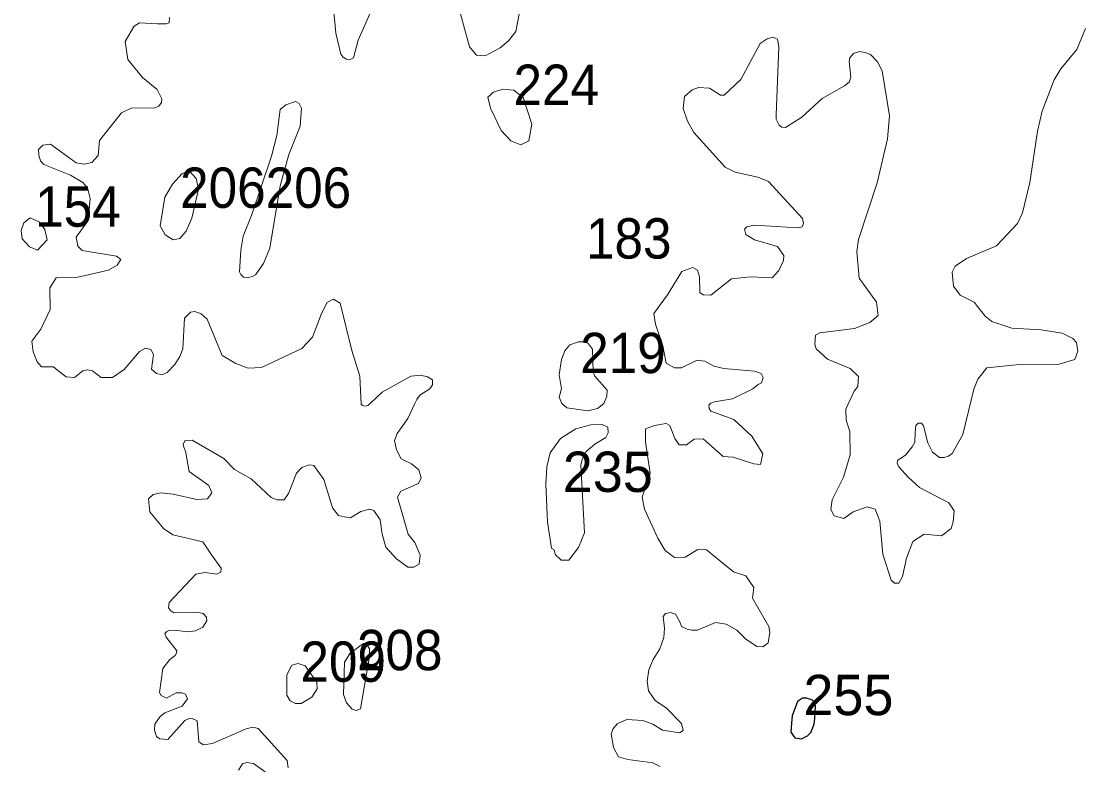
# Model space of a CAD drawing. Extents: x 499.9 to 555.3, y 9281.5 to 9336.8.
# Drawn here: x 531.687 to 535.902, y 9318.048 to 9320.996 of the extents above; entities that cross this region are included whole.
import ezdxf

# ---------------------------------------------------------------- set-up
doc = ezdxf.new("R2010")
doc.units = 0
doc.header["$LTSCALE"] = 0.064
doc.layers.add('1', color=7, linetype='Continuous', lineweight=25)
doc.layers.add('2', color=7, linetype='Continuous', lineweight=13)
doc.layers.add('21', color=7, linetype='Continuous')

msp = doc.modelspace()

# ---------------------------------------------------------------- linework, layer by layer
at = {"layer": '1'}
msp.add_lwpolyline([(534.7641, 9318.2991), (534.742, 9318.2417), (534.7398, 9318.213), (534.7376, 9318.1776), (534.7531, 9318.1555), (534.7796, 9318.1511), (534.8039, 9318.1622), (534.8171, 9318.1754), (534.8304, 9318.2085), (534.8326, 9318.2329), (534.8348, 9318.2815), (534.8238, 9318.3036), (534.7995, 9318.3124), (534.784, 9318.3124)], close=True, dxfattribs=at)
at = {"layer": '2'}
for points in [[(533.6286, 9321.0929), (533.6287, 9321.1259), (533.6434, 9321.176), (533.6602, 9321.2062), (533.6936, 9321.2341), (533.7271, 9321.2793), (533.7441, 9321.3288), (533.7427, 9321.3663), (533.7313, 9321.3942), (533.7039, 9321.4154), (533.6836, 9321.4604), (533.6861, 9321.5429), (533.6718, 9321.5701), (533.6455, 9321.5583), (533.5168, 9321.4), (533.4556, 9321.2382), (533.4241, 9321.0402), (533.4637, 9320.8945), (533.4912, 9320.8609), (533.5249, 9320.8586), (533.5854, 9320.8908), (533.6179, 9320.9183), (533.6467, 9320.9556), (533.6607, 9321.0243)], [(533.6268, 9320.5221), (533.6673, 9320.506), (533.6992, 9320.5212), (533.7106, 9320.5874), (533.6756, 9320.6938), (533.6386, 9320.7231), (533.5955, 9320.7263), (533.5583, 9320.7146), (533.5355, 9320.6947), (533.5463, 9320.6511), (533.5883, 9320.5629)], [(532.5659, 9320.1437), (532.5998, 9320.2263), (532.6786, 9320.4608), (532.6993, 9320.5435), (532.7124, 9320.6454), (532.7348, 9320.6651), (532.774, 9320.6772), (532.7884, 9320.6697), (532.798, 9320.6508), (532.7918, 9320.5799), (532.7473, 9320.4678), (532.7123, 9320.3437), (532.6714, 9320.0958), (532.6473, 9320.0357), (532.6152, 9319.9912), (532.6058, 9319.9853), (532.5875, 9319.9805), (532.5673, 9319.9815), (532.5564, 9319.9925), (532.5518, 9320.0022), (532.5564, 9320.0884)], [(532.2564, 9320.1487), (532.2373, 9320.1849), (532.2553, 9320.2982), (532.2863, 9320.3501), (532.3245, 9320.3929), (532.3535, 9320.401), (532.38, 9320.3726), (532.3887, 9320.3298), (532.3633, 9320.2157), (532.3401, 9320.1638), (532.3154, 9320.1341), (532.289, 9320.1292)], [(531.719, 9320.1018), (531.69, 9320.1335), (531.6865, 9320.1664), (531.6971, 9320.1971), (531.7217, 9320.2161), (531.7589, 9320.1992), (531.7801, 9320.1702), (531.7887, 9320.1292), (531.751, 9320.0879)], [(533.8286, 9319.5386), (533.8189, 9319.5058), (533.8288, 9319.4801), (533.8489, 9319.4634), (533.9325, 9319.4518), (533.9712, 9319.4607), (533.9956, 9319.4807), (534.0073, 9319.51), (534.0085, 9319.5331), (533.9599, 9319.5888), (533.9535, 9319.6048), (533.9506, 9319.6963), (533.9356, 9319.7168), (533.9201, 9319.7247), (533.8961, 9319.7248), (533.8617, 9319.7134), (533.8418, 9319.6896), (533.8284, 9319.655), (533.8183, 9319.5947)], [(533.7729, 9319.0118), (533.7655, 9319.1605), (533.7701, 9319.2296), (533.7826, 9319.2851), (533.8242, 9319.3414), (533.885, 9319.3801), (533.9447, 9319.3957), (533.9894, 9319.3969), (534.0112, 9319.3868), (534.0135, 9319.3644), (534.0044, 9319.3459), (533.96, 9319.3193), (533.9256, 9319.2902), (533.9111, 9319.2629), (533.9051, 9319.2372), (533.9187, 9318.9671), (533.896, 9318.9091), (533.8568, 9318.8587), (533.8273, 9318.8593), (533.8047, 9318.8806), (533.7975, 9318.9014), (533.7883, 9318.9074)], [(532.9683, 9318.4555), (532.9633, 9318.3263), (532.9759, 9318.2932), (532.9979, 9318.2682), (533.014, 9318.2634), (533.031, 9318.2695), (533.0672, 9318.4777), (533.0672, 9318.5072), (533.0568, 9318.5255), (533.0428, 9318.5286), (532.99, 9318.4905)], [(532.8578, 9318.3761), (532.8123, 9318.4403), (532.784, 9318.4493), (532.7585, 9318.4425), (532.739, 9318.4052), (532.7397, 9318.3236), (532.7523, 9318.3016), (532.7735, 9318.2906), (532.7962, 9318.2913), (532.8384, 9318.3156), (532.8589, 9318.349)]]:
    msp.add_lwpolyline(points, close=True, dxfattribs=at)
for points in [[(533.0786, 9321.0494), (533.0214, 9320.9205), (533.0031, 9320.8503), (532.9901, 9320.8443), (532.9751, 9320.8455), (532.9613, 9320.8545), (532.9533, 9320.866), (532.9341, 9320.9483), (532.9252, 9321.0352)], [(532.2738, 9321.0111), (532.2722, 9320.9903), (532.261, 9320.9859), (532.226, 9320.9853), (532.1547, 9320.9894), (532.1347, 9320.977), (532.0981, 9320.9159), (532.109, 9320.8442), (532.1669, 9320.7729), (532.2255, 9320.7248), (532.2438, 9320.6882), (532.2427, 9320.6738), (532.2315, 9320.6591), (532.2163, 9320.6528), (532.1221, 9320.6511), (532.0832, 9320.6327), (531.9972, 9320.5236), (531.9908, 9320.4641), (531.9667, 9320.436), (531.9355, 9320.4298), (531.9039, 9320.4346), (531.8019, 9320.5088), (531.7724, 9320.5044), (531.7545, 9320.4878), (531.7557, 9320.4644), (531.7633, 9320.4424), (531.776, 9320.4286), (531.8814, 9320.3851), (531.9307, 9320.3563), (531.9484, 9320.3349), (531.9592, 9320.2928)], [(535.5147, 9319.6221), (535.6305, 9319.6338), (535.796, 9319.6354), (535.8632, 9319.6548), (535.8748, 9319.6881), (535.8696, 9319.7229), (535.8549, 9319.7377), (535.8133, 9319.7592), (535.7299, 9319.7723), (535.6138, 9319.7785), (535.5344, 9319.8053), (535.5071, 9319.8265), (535.4638, 9319.882), (535.4079, 9319.91), (535.3816, 9319.9459), (535.3765, 9320.0014), (535.3891, 9320.025), (535.4332, 9320.0551), (535.5522, 9320.1056), (535.6358, 9320.1941), (535.6558, 9320.237), (535.6853, 9320.3564), (535.7145, 9320.5603), (535.7331, 9320.6397), (535.7809, 9320.7639), (535.8074, 9320.8068), (535.8714, 9320.8833), (535.9048, 9320.9677)], [(534.3271, 9320.5998), (534.3099, 9320.65), (534.3163, 9320.6974), (534.3459, 9320.7242), (534.3715, 9320.7335), (534.4151, 9320.7302), (534.4585, 9320.7027), (534.473, 9320.7025), (534.5392, 9320.7656), (534.6156, 9320.9081), (534.6429, 9320.9261), (534.666, 9320.9333), (534.6846, 9320.9248), (534.6901, 9320.8947), (534.6795, 9320.6246), (534.6792, 9320.6077), (534.691, 9320.5844), (534.701, 9320.5758), (534.7164, 9320.5745), (534.7806, 9320.616), (534.862, 9320.6901), (534.9495, 9320.7399), (534.968, 9320.7544), (534.9753, 9320.7743), (534.969, 9320.8364), (534.9717, 9320.851), (534.9854, 9320.8686), (535.01, 9320.8756), (535.0311, 9320.8725), (535.0528, 9320.8638), (535.0804, 9320.8353), (535.0992, 9320.7996), (535.1281, 9320.6214), (535.1206, 9320.5302), (535.079, 9320.3558), (535.0051, 9320.1306), (534.9994, 9320.0835), (535.0075, 9319.9767), (535.0764, 9319.882), (535.0837, 9319.8295), (535.0507, 9319.8012), (534.989, 9319.7774), (534.8523, 9319.7601), (534.8356, 9319.7507), (534.8324, 9319.716), (534.8381, 9319.6975), (534.882, 9319.6556), (534.9722, 9319.6194), (535.0055, 9319.5875), (535.0022, 9319.5481), (534.988, 9319.5297), (534.955, 9319.458), (534.9565, 9319.4142), (534.9706, 9319.3697), (534.9723, 9319.2774), (534.9455, 9319.189), (534.9008, 9319.0991), (534.8963, 9319.0596), (534.9095, 9319.0354), (534.9479, 9319.0246), (534.9844, 9319.0508), (535.0392, 9319.0702), (535.0712, 9319.0614), (535.0902, 9319.0145), (535.1014, 9318.8826), (535.1348, 9318.7794), (535.1485, 9318.7687), (535.1656, 9318.7684), (535.1793, 9318.7942), (535.1955, 9318.8674), (535.2212, 9318.9339), (535.2652, 9318.9619), (535.3341, 9318.9564), (535.3726, 9318.9842), (535.3813, 9319.0108), (535.3842, 9319.0544), (535.3637, 9319.0862), (535.2478, 9319.148), (535.2036, 9319.187), (535.1639, 9319.2305), (535.1591, 9319.2433), (535.1607, 9319.2538), (535.1933, 9319.2773), (535.2188, 9319.308), (535.2291, 9319.3269), (535.2298, 9319.3638), (535.2334, 9319.3928), (535.2416, 9319.403), (535.2554, 9319.4031), (535.2631, 9319.3916), (535.2807, 9319.3248), (535.2995, 9319.2874), (535.3267, 9319.2668), (535.3454, 9319.2667), (535.3628, 9319.272)], [(534.6488, 9320.3602), (534.6069, 9320.3784), (534.5164, 9320.3982), (534.4775, 9320.4171), (534.3532, 9320.5555), (534.3271, 9320.5998)], [(534.2307, 9318.6359), (534.2408, 9318.6477), (534.2606, 9318.6512), (534.2797, 9318.6451), (534.2975, 9318.6143), (534.3039, 9318.5969), (534.3262, 9318.5852), (534.3443, 9318.5814), (534.3675, 9318.5821), (534.4383, 9318.6119), (534.4803, 9318.606), (534.5235, 9318.5817), (534.5575, 9318.548), (534.6031, 9318.5169), (534.6268, 9318.5154), (534.6476, 9318.5318), (534.6539, 9318.5739), (534.6506, 9318.5961), (534.5848, 9318.709), (534.5903, 9318.7509), (534.5593, 9318.7969), (534.5101, 9318.8131), (534.4033, 9318.9), (534.3684, 9318.9015), (534.3181, 9318.8707), (534.2758, 9318.8694), (534.2392, 9318.8981), (534.21, 9318.9463), (534.1575, 9319.0619), (534.1483, 9319.1085), (534.1795, 9319.2041), (534.1609, 9319.3265), (534.1609, 9319.3796), (534.1964, 9319.3937), (534.2427, 9319.4011), (534.2579, 9319.3934), (534.2772, 9319.3412), (534.2945, 9319.3168), (534.3241, 9319.3168), (534.3537, 9319.3394), (534.3897, 9319.3405), (534.4688, 9319.2697), (534.5093, 9319.2674), (534.5911, 9319.2407), (534.6164, 9319.2389), (534.6266, 9319.2811), (534.5832, 9319.351), (534.5111, 9319.4169), (534.4197, 9319.4504), (534.4134, 9319.4608), (534.4125, 9319.4732), (534.4205, 9319.4816), (534.4351, 9319.4874), (534.5062, 9319.4993), (534.5871, 9319.5384), (534.6073, 9319.5563), (534.6216, 9319.563), (534.6272, 9319.5833), (534.6203, 9319.599), (534.5933, 9319.6085), (534.4718, 9319.6197), (534.432, 9319.629), (534.3968, 9319.6478), (534.3657, 9319.6526), (534.3038, 9319.6214), (534.2762, 9319.6215), (534.2436, 9319.6405), (534.2302, 9319.7089), (534.2008, 9319.7955), (534.1945, 9319.8374), (534.2481, 9319.9108), (534.3051, 9320.0038), (534.3489, 9320.0201), (534.3676, 9320.0086), (534.3753, 9319.9832), (534.3769, 9319.9203), (534.3899, 9319.9108), (534.42, 9319.9103), (534.5019, 9319.9746), (534.5769, 9319.9824), (534.6633, 9319.9781), (534.6898, 9320.008), (534.708, 9320.0477), (534.7099, 9320.0674), (534.6842, 9320.1024), (534.5936, 9320.129), (534.5588, 9320.1501), (534.5531, 9320.1712), (534.5625, 9320.1813), (534.5915, 9320.1875), (534.7661, 9320.1768), (534.7826, 9320.1802), (534.7874, 9320.1941), (534.7841, 9320.2133), (534.6488, 9320.3602)], [(531.9592, 9320.2928), (531.9516, 9320.2055), (531.9042, 9320.1398), (531.9108, 9320.1045), (531.9284, 9320.0874), (532.0644, 9320.065)], [(532.0644, 9320.065), (532.0813, 9320.0507), (532.0669, 9320.0283), (532.0318, 9320.0084), (531.9102, 9319.9812), (531.8245, 9319.9793), (531.7991, 9319.9394), (531.8006, 9319.8535), (531.7641, 9319.7746), (531.729, 9319.7269), (531.7331, 9319.6848), (531.7491, 9319.6458), (531.7671, 9319.6263), (531.8142, 9319.6256), (531.8313, 9319.6111), (531.8641, 9319.586), (531.8978, 9319.5833), (531.9309, 9319.6098), (531.9492, 9319.614), (531.9688, 9319.6097), (532.0032, 9319.583), (532.0482, 9319.5834), (532.0946, 9319.6148), (532.1553, 9319.686), (532.1793, 9319.6993), (532.2005, 9319.6942), (532.2113, 9319.6744), (532.207, 9319.6454), (532.2027, 9319.6166), (532.2226, 9319.5998), (532.2451, 9319.5945), (532.2645, 9319.6027), (532.2954, 9319.6346), (532.3146, 9319.6674), (532.3269, 9319.6976), (532.3338, 9319.8184), (532.3575, 9319.8421), (532.3742, 9319.8452), (532.3993, 9319.836), (532.4228, 9319.8145), (532.4828, 9319.6713), (532.5366, 9319.639), (532.5863, 9319.6203), (532.6383, 9319.6228), (532.7987, 9319.6982), (532.8414, 9319.7429), (532.8761, 9319.8369), (532.8993, 9319.8804), (532.9239, 9319.8943), (532.9511, 9319.8781), (532.9972, 9319.6912), (533.0288, 9319.5893), (533.0338, 9319.4784), (533.0386, 9319.4723), (533.0501, 9319.4695), (533.0607, 9319.4723), (533.0728, 9319.4825), (533.1167, 9319.5255), (533.2313, 9319.5892), (533.2693, 9319.5923), (533.2966, 9319.5861), (533.3168, 9319.5742), (533.3161, 9319.5546), (533.3056, 9319.5383), (533.2659, 9319.5128), (533.2547, 9319.4958), (533.2467, 9319.4808), (533.2187, 9319.4205), (533.1763, 9319.3613), (533.1662, 9319.3336), (533.174, 9319.2965), (533.1927, 9319.2607), (533.2332, 9319.2416), (533.2621, 9319.2172), (533.272, 9319.1852), (533.2611, 9319.163), (533.1911, 9319.1333), (533.1774, 9319.1095), (533.2208, 9318.963), (533.2473, 9318.9296), (533.2676, 9318.8796), (533.2633, 9318.8428), (533.2427, 9318.8314), (533.2185, 9318.8314), (533.1739, 9318.8652), (533.1315, 9318.9108), (533.1166, 9318.9623), (533.1099, 9319.0194), (533.0846, 9319.0558), (533.0681, 9319.0621), (533.0322, 9319.0518), (532.9917, 9319.0265), (532.9679, 9319.0314), (532.9441, 9319.0364), (532.9204, 9319.0666)], [(535.3628, 9319.272), (535.3763, 9319.2823), (535.4185, 9319.3572), (535.4632, 9319.5369), (535.479, 9319.5772), (535.5147, 9319.6221)], [(532.7774, 9319.2038), (532.7459, 9319.1237), (532.7283, 9319.0984), (532.7011, 9319.099), (532.6778, 9319.1074), (532.5977, 9319.1817), (532.5319, 9319.2191), (532.4893, 9319.2629), (532.3646, 9319.335), (532.3364, 9319.3339), (532.3279, 9319.3191), (532.3308, 9319.3076), (532.3369, 9319.2917), (532.3516, 9319.2107), (532.4303, 9319.1547), (532.4426, 9319.1257), (532.4253, 9319.1027), (532.383, 9319.0993), (532.2881, 9319.1215), (532.2412, 9319.126), (532.2094, 9319.1201), (532.1903, 9319.1025), (532.1966, 9319.0506), (532.2502, 9318.9852), (532.2874, 9318.9601), (532.4069, 9318.9321), (532.4405, 9318.8798), (532.4793, 9318.8282), (532.4774, 9318.812), (532.4621, 9318.8039), (532.4156, 9318.8109), (532.3789, 9318.8033), (532.2726, 9318.6915), (532.2706, 9318.6706), (532.2788, 9318.6579), (532.2911, 9318.6507), (532.39, 9318.6517), (532.4078, 9318.6478), (532.4206, 9318.6336), (532.4222, 9318.6186), (532.4068, 9318.5943), (532.3771, 9318.5794), (532.3484, 9318.5753), (532.2932, 9318.5812), (532.2716, 9318.5799), (532.2636, 9318.577), (532.2559, 9318.5679), (532.2605, 9318.5536), (532.303, 9318.5), (532.3025, 9318.49), (532.2971, 9318.481), (532.2751, 9318.4661), (532.248, 9318.4295), (532.2351, 9318.3345), (532.2407, 9318.3223), (532.2626, 9318.3121), (532.3011, 9318.3331), (532.324, 9318.3336), (532.3372, 9318.3275), (532.3457, 9318.3091), (532.3248, 9318.2808), (532.2555, 9318.2546), (532.2366, 9318.2395), (532.2159, 9318.2086), (532.2147, 9318.1853), (532.2227, 9318.1597), (532.2357, 9318.1506), (532.2672, 9318.148), (532.335, 9318.2234), (532.3489, 9318.2298), (532.3642, 9318.232), (532.3839, 9318.2217), (532.3906, 9318.139), (532.4088, 9318.1268), (532.4441, 9318.1324), (532.578, 9318.19), (532.604, 9318.1967), (532.6261, 9318.1916), (532.7405, 9318.0652), (532.744, 9318.0366)], [(532.9204, 9319.0666), (532.8866, 9319.1785), (532.8458, 9319.2341), (532.8287, 9319.2368), (532.7981, 9319.2272), (532.7774, 9319.2038)], [(534.1737, 9318.425), (534.1909, 9318.4657), (534.2178, 9318.5071), (534.2338, 9318.5526), (534.2368, 9318.5898), (534.2307, 9318.6359)], [(534.2188, 9318.0409), (534.1897, 9318.0562), (534.0905, 9318.0685), (534.0545, 9318.0802), (534.0343, 9318.1163), (534.0254, 9318.1688), (534.031, 9318.1892), (534.0493, 9318.2107), (534.0875, 9318.2271), (534.1501, 9318.2234), (534.1897, 9318.209), (534.2289, 9318.1853), (534.2957, 9318.1751), (534.3103, 9318.1841), (534.3042, 9318.2115), (534.2447, 9318.2725), (534.1994, 9318.3033), (534.1736, 9318.3416), (534.1674, 9318.3796), (534.1737, 9318.425)], [(532.6529, 9318.0205), (532.6071, 9318.0531), (532.5801, 9318.0576), (532.5639, 9318.0521), (532.5471, 9318.0269)]]:
    msp.add_lwpolyline(points, dxfattribs=at)

# ---------------------------------------------------------------- texts
at = {"layer": '21', "width": 0.95}
for s, p in [('224', (533.6378, 9320.664)), ('206', (532.3162, 9320.256)), ('206', (532.6552, 9320.256)), ('154', (531.7416, 9320.1813)), ('183', (533.9251, 9320.0549)), ('219', (533.9022, 9319.6009)), ('208', (533.0172, 9318.4229)), ('209', (532.7931, 9318.377))]:
    msp.add_text(s, height=0.16, dxfattribs=at).set_placement(p)
at = {"layer": '21'}
for s, p in [('235', (533.8332, 9319.1297)), ('255', (534.7871, 9318.2448))]:
    msp.add_text(s, height=0.16, dxfattribs=at).set_placement(p)

doc.saveas('drawing.dxf')
